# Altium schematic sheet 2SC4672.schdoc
size 127 x 101 mm
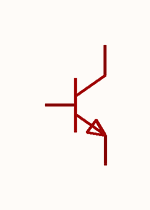
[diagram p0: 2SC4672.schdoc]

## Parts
Q?  2sc4672(range:180-390)  [SOT-89-3_L4.5-W2.5-P1.50-LS4.2-BR]  (value not drawn)

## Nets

Not connected (* = marked no-connect by the designer): Q? 1(B) 2(C) 3(E)

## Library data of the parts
Q? = 2sc4672(range:180-390): 晶体管类型:NPN;集电极电流(Ic):2A;集射极击穿电压(Vceo):50V;耗散功率(Pd):500mW;直流电流增益(hFE):180;; Manufacturer: CJ(江苏长电/长晶); AddInBom: yes; ModelId: 6db690b7897d4d18a30d90c1b89525ee; ModelName: SOT-89-3_L4.3-W2.5-H1.6-LS4.1-P1.50; ModelTransform: 161.417,169.291,0,180,0,0,-18.661,0,0; type: NPN; Current - Collector(Ic): 2A; Collector - Emitter Voltage VCEO: 50V; Pd - Power Dissipation: 500mW; DC Current Gain: 180; Transition frequency(fT): 210MHz; Current - Collector Cutoff: 100nA; Vce Saturation(VCE(sat)): 350mV; Emitter-Base Voltage(Vebo): 6V; Number: 1个NPN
